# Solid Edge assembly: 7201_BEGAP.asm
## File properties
Author: PARTuser1
Template: Normal.asm
Last saved by: PARTuser1
Revision: 1
Application: Solid Edge
CADENASNORM: 7201 BEGAP
CADENAS_NB: 7201 BEGAP
CADENAS_NBSYN: 7201 BEGAP
CADENAS_LINA: 7201 BEGAP
CADENAS_PSOL_MULTISOLIDPART: 0
CADENAS_Z: 10.000
CADENAS_Y0W2: 10.604
CADENAS_XIP: 0.000
CADENAS_XIN: 0.000
CADENAS_YIAC: 10.100
CADENAS_HIAC: 4.100
CADENAS_BEAC: 10.000
CADENAS_HI1: 2.250
CADENAS_R2I: 0.200
CADENAS_RWB: 3.000
CADENAS_XEP: 0.000
CADENAS_R2E: 0.100
CADENAS_Z0W2: 3.446
CADENAS_XEN: 0.000
CADENAS_RI: 3.000
CADENAS_X0WB: 5.000
CADENAS_RE: 3.000
CADENAS_C1E: 0.000
CADENAS_HE2: -16.000
CADENAS_HE1: 1.900
CADENAS_YEAC: 12.550
CADENAS_HEAC: 3.450
CADENAS_X0W2: 5.000
CADENAS_BOREDIAMETER: 12.000
CADENAS_BIAC: 10.000
CADENAS_BCH: 0.000
CADENAS_R1I: 0.600
CADENAS_PRODUCTID: 1210023201.000
CADENAS_BEARINGWIDTH: 10.000
CADENAS_R1E: 0.300
CADENAS_Y0WE: 11.150
CADENAS_Y0WB: 11.150
CADENAS_X0IP: 5.000
CADENAS_Y0IAC: 11.150
CADENAS_comment: design:acbb1; version:5000.3; lang:it; selectedUnitParts:000000; action:download; skf2d3daction.jsp version:2008-03-06; getRequestURI:/skf/skf3dnew/skf2d3daction.jsp
CADENAS_KT: DUMMY
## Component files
7201_BEGAP_PART1.par
7201_BEGAP_PART2.par
7201_BEGAP_PART3.par
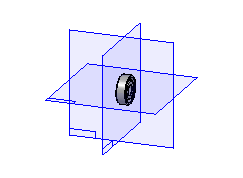
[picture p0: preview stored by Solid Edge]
